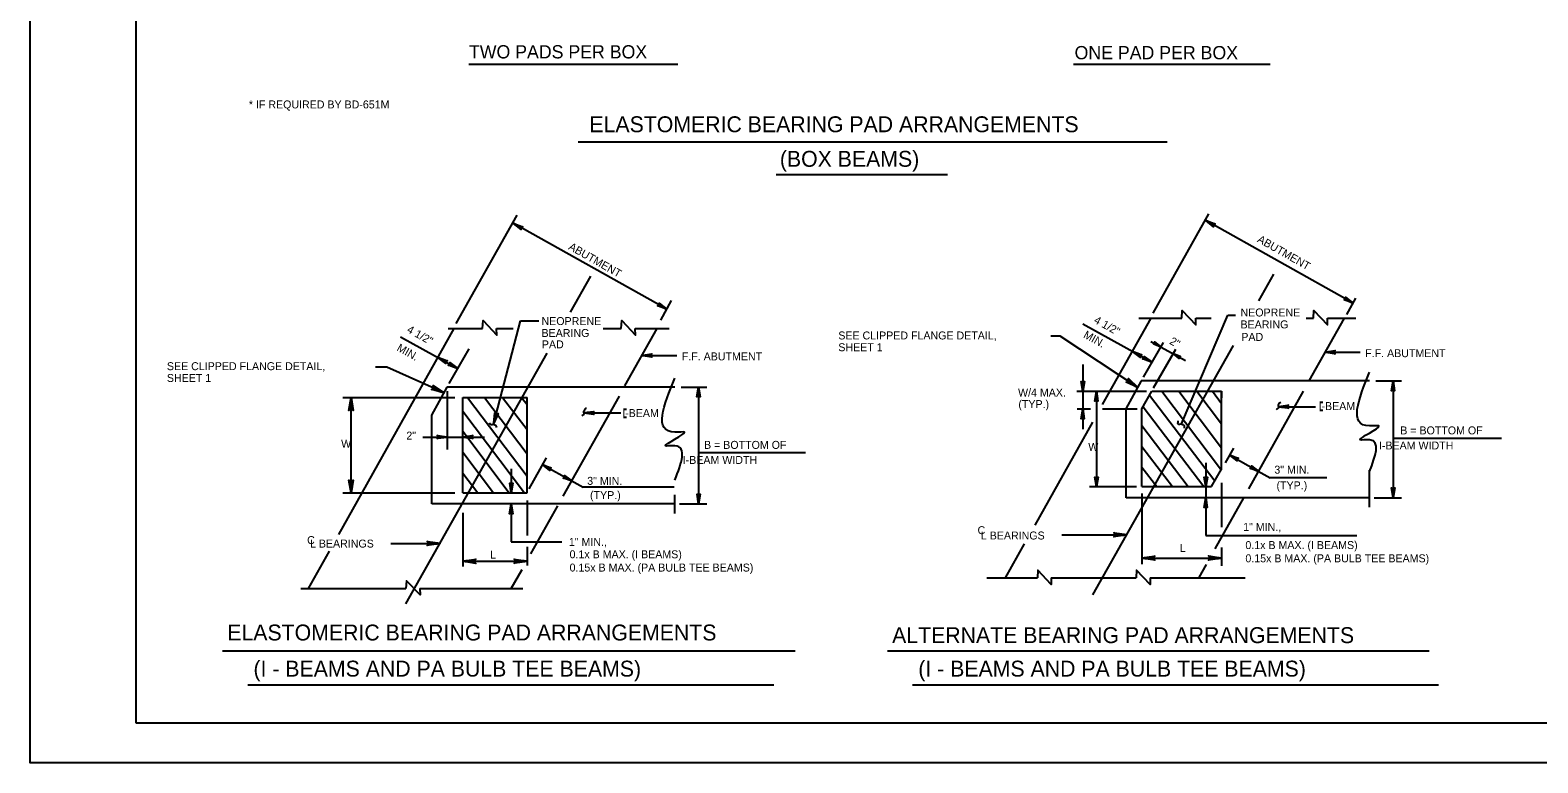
# Model space of a CAD drawing. Extents: x 639028 to 640031, y 298558 to 299746.
# Drawn here: x 639028 to 639597, y 298558 to 298835 of the extents above; entities that cross this region are included whole.
import ezdxf

# ---------------------------------------------------------------- set-up
doc = ezdxf.new("R2010")
doc.units = 0
doc.layers.add('1', color=7, linetype='Continuous')
doc.layers.add('PLT-BNDY', color=7, linetype='Continuous')

msp = doc.modelspace()

# ---------------------------------------------------------------- linework, layer by layer
at = {"layer": '1'}
for p, q in [((639067.87, 298573.33), (639067.87, 299137.33)), ((639193.44, 298821.9), (639272.25, 298821.9)), ((639421.49, 298821.9), (639495.7, 298821.9)), ((639234.68, 298792.59), (639456.81, 298792.59)), ((639309.33, 298780.24), (639373.96, 298780.24)), ((639188.59, 298724.09), (639211.59, 298764.96)), ((639268.09, 298729.46), (639210.09, 298761.96)), ((639451.57, 298727.98), (639472.58, 298765.41)), ((639527.1, 298731.76), (639471.48, 298762.89)), ((639231.73, 298728.37), (639239.39, 298741.96)), ((639491.42, 298732.69), (639497.05, 298742.67)), ((639265.84, 298725.34), (639269.84, 298732.71)), ((639524.7, 298727.48), (639528.09, 298733.6)), ((639432.5, 298693.5), (639450.79, 298726.1)), ((639446.2, 298726.1), (639462.39, 298726.1)), ((639462.23, 298686.17), (639479.73, 298727.17)), ((639467.64, 298726.1), (639473.52, 298726.1)), ((639479.73, 298727.17), (639482.6, 298727.17)), ((639509.37, 298726.1), (639512.05, 298726.1)), ((639510.48, 298702.42), (639523.83, 298726.1)), ((639517.3, 298726.1), (639528.07, 298726.1)), ((639144.34, 298644.49), (639187.86, 298722.21)), ((639185.59, 298722.21), (639198.58, 298722.21)), ((639202.88, 298686.52), (639212.85, 298725.11)), ((639203.83, 298722.21), (639210.14, 298722.21)), ((639212.85, 298725.11), (639219.81, 298725.11)), ((639244.1, 298722.21), (639250.88, 298722.21)), ((639252.25, 298700.54), (639264.47, 298722.21)), ((639256.13, 298722.21), (639268.97, 298722.21)), ((639425.01, 298723.98), (639451.19, 298709.44)), ((639167.55, 298719.1), (639189.21, 298707.06)), ((639186, 298701.42), (639193.48, 298714.57)), ((639416.55, 298719.31), (639413.02, 298719.31)), ((639445.86, 298699.97), (639416.55, 298719.31)), ((639428.86, 298621.71), (639481.87, 298715.73)), ((639447.98, 298703.79), (639455.45, 298716.94)), ((639450.69, 298717.35), (639463.78, 298710.08)), ((639451.73, 298699.79), (639460.17, 298714.43)), ((639169.67, 298618.29), (639222.97, 298712.83)), ((639258.74, 298712.05), (639271.87, 298712.05)), ((639425.1, 298708.64), (639425.1, 298684.21)), ((639516.59, 298713.26), (639529.72, 298713.26)), ((639162.47, 298707.6), (639158.21, 298707.6)), ((639184.08, 298697.95), (639162.47, 298707.6)), ((639179.38, 298689.54), (639185.25, 298700.04)), ((639271.13, 298700.04), (639185.13, 298700.04)), ((639185.38, 298676.54), (639185.38, 298698.54)), ((639273.5, 298700.04), (639283.13, 298700.04)), ((639280, 298700.04), (639280, 298656.04)), ((639422.73, 298698.54), (639449.1, 298698.54)), ((639430.23, 298698.54), (639430.23, 298662.54)), ((639441.35, 298691.92), (639447.23, 298702.42)), ((639533.23, 298702.42), (639447.1, 298702.42)), ((639447.35, 298691.92), (639451.1, 298698.54)), ((639451.1, 298698.54), (639477.35, 298698.54)), ((639454.85, 298698.54), (639477.35, 298668.79)), ((639461.23, 298698.54), (639477.35, 298677.17)), ((639468.1, 298698.54), (639477.35, 298686.29)), ((639473.98, 298698.54), (639477.35, 298693.92)), ((639477.35, 298669.17), (639477.35, 298698.54)), ((639477.35, 298698.54), (639477.36, 298696.06)), ((639487.67, 298661.72), (639508.29, 298698.51)), ((639535.6, 298702.42), (639545.23, 298702.42)), ((639542.1, 298702.42), (639542.1, 298658.29)), ((639145.83, 298696.17), (639188.14, 298696.17)), ((639148.94, 298660.17), (639148.94, 298696.17)), ((639191.13, 298696.17), (639215.38, 298696.17)), ((639191.13, 298660.17), (639191.13, 298696.17)), ((639192.88, 298696.17), (639215.38, 298666.54)), ((639199.25, 298696.17), (639215.38, 298674.92)), ((639206.13, 298696.17), (639215.38, 298684.04)), ((639213.25, 298696.17), (639215.38, 298693.54)), ((639215.38, 298660.17), (639215.38, 298696.17)), ((639229.04, 298658.92), (639250.19, 298696.72)), ((639251.75, 298691.79), (639252.88, 298691.79)), ((639422.85, 298691.92), (639427.99, 298691.92)), ((639432.52, 298691.92), (639445.6, 298691.92)), ((639441.35, 298658.29), (639441.35, 298691.92)), ((639447.35, 298662.54), (639447.35, 298691.92)), ((639447.85, 298692.67), (639470.73, 298662.54)), ((639450.23, 298697.04), (639474.85, 298664.67)), ((639498.85, 298692.67), (639512.85, 298692.67)), ((639514.48, 298694.42), (639515.6, 298694.42)), ((639179.38, 298656.04), (639179.38, 298689.54)), ((639191.13, 298691.04), (639214.38, 298660.17)), ((639236.88, 298690.42), (639250.75, 298690.42)), ((639251.75, 298688.79), (639252.88, 298688.79)), ((639407.01, 298648.06), (639428.76, 298686.83)), ((639514.48, 298691.42), (639515.6, 298691.42)), ((639176.04, 298681.17), (639185.13, 298681.17)), ((639185.13, 298681.17), (639191.13, 298681.17)), ((639191.13, 298683.42), (639208.63, 298660.17)), ((639191.13, 298681.17), (639199.25, 298681.17)), ((639447.35, 298685.54), (639464.85, 298662.54)), ((639542.1, 298680.82), (639583.07, 298680.82)), ((639191.13, 298675.54), (639202.75, 298660.17)), ((639280.14, 298675.36), (639320.38, 298675.36)), ((639447.35, 298677.67), (639458.85, 298662.54)), ((639478.85, 298671.54), (639481.98, 298677.04)), ((639209.38, 298669.29), (639209.38, 298660.17)), ((639216.13, 298661.67), (639222.75, 298673.42)), ((639221.25, 298670.79), (639232.25, 298664.67)), ((639447.35, 298669.92), (639452.98, 298662.54)), ((639471.48, 298671.54), (639471.48, 298662.54)), ((639473.6, 298662.54), (639477.35, 298669.17)), ((639480.48, 298674.42), (639491.48, 298668.29)), ((639533.23, 298661.41), (639533.23, 298668.73)), ((639191.13, 298667.67), (639196.75, 298660.17)), ((639232, 298664.79), (639236.5, 298662.29)), ((639477.35, 298663.94), (639477.35, 298647.29)), ((639491.23, 298668.42), (639495.73, 298665.92)), ((639517.16, 298665.92), (639495.73, 298665.92)), ((639145.83, 298660.17), (639188.14, 298660.17)), ((639191.13, 298660.17), (639215.38, 298660.17)), ((639270.84, 298662.29), (639236.5, 298662.29)), ((639271.13, 298652.42), (639271.13, 298659.42)), ((639427.6, 298662.54), (639445.35, 298662.54)), ((639533.23, 298658.29), (639441.35, 298658.29)), ((639447.35, 298662.54), (639473.6, 298662.54)), ((639447.35, 298659.92), (639447.35, 298633.3)), ((639471.48, 298662.54), (639471.48, 298644.04)), ((639475.01, 298639.06), (639485.85, 298658.29)), ((639533.23, 298654.79), (639533.23, 298662.92)), ((639534.98, 298658.29), (639545.23, 298658.29)), ((639271.13, 298656.04), (639179.38, 298656.04)), ((639191.13, 298652.68), (639191.13, 298632.45)), ((639209.38, 298656.04), (639209.38, 298641.67)), ((639215.38, 298657.32), (639215.38, 298644.04)), ((639216.78, 298637.14), (639227, 298655.29)), ((639272.88, 298656.04), (639283.13, 298656.04)), ((639163.93, 298641.08), (639182.52, 298641.08)), ((639209.38, 298641.67), (639228.5, 298641.67)), ((639395.83, 298628.13), (639402.99, 298640.9)), ((639417.14, 298644.38), (639441.64, 298644.38)), ((639471.48, 298644.04), (639528.43, 298644.04)), ((639132.89, 298624.05), (639140.82, 298638.2)), ((639215.38, 298639.85), (639215.38, 298632.78)), ((639447.35, 298635.59), (639477.35, 298635.59)), ((639477.35, 298639.56), (639477.35, 298632.64)), ((639191.13, 298634.38), (639215.38, 298634.38)), ((639209.41, 298624.05), (639213.47, 298631.25)), ((639468.92, 298628.25), (639471.68, 298633.15)), ((639130.02, 298624.05), (639169.64, 298624.05)), ((639174.89, 298624.05), (639213.77, 298624.05)), ((639388.82, 298628.12), (639407.9, 298628.12)), ((639413.15, 298628.12), (639445.17, 298628.12)), ((639450.42, 298628.12), (639486.3, 298628.12)), ((639100.5, 298600.62), (639316.46, 298600.62)), ((639351.34, 298600.62), (639555.72, 298600.62)), ((639110, 298587.75), (639308.41, 298587.75)), ((639360.84, 298587.75), (639559.25, 298587.75)), ((639853.87, 298573.33), (639067.87, 298573.33))]:
    msp.add_line(p, q, dxfattribs=at)
for points in [[(639212.97, 298759.71), (639212.97, 298760.09), (639210.22, 298761.84), (639212.97, 298759.71), (639213.09, 298759.59), (639210.22, 298761.84), (639213.22, 298760.34), (639213.47, 298760.46), (639210.22, 298761.84), (639213.72, 298760.59), (639213.47, 298760.46)], [(639474.35, 298760.76), (639474.35, 298761.01), (639471.48, 298762.89), (639474.35, 298760.76), (639474.35, 298760.51), (639471.48, 298762.89), (639474.48, 298761.39), (639474.73, 298761.51), (639471.48, 298762.89), (639474.98, 298761.64), (639474.73, 298761.51)], [(639265.22, 298731.59), (639265.22, 298731.21), (639268.09, 298729.46), (639265.22, 298731.59), (639265.22, 298731.71), (639268.09, 298729.46), (639265.09, 298730.96), (639264.84, 298730.84), (639268.09, 298729.46), (639264.59, 298730.71), (639264.84, 298730.84)], [(639524.23, 298733.89), (639524.23, 298733.51), (639527.1, 298731.76), (639524.23, 298733.89), (639524.1, 298734.01), (639527.1, 298731.76), (639524.1, 298733.26), (639523.85, 298733.14), (639527.1, 298731.76), (639523.6, 298733.01), (639523.85, 298733.14)], [(639462.39, 298726.1), (639462.51, 298728.98), (639467.64, 298723.6), (639467.64, 298726.1)], [(639512.05, 298726.1), (639512.18, 298728.98), (639517.3, 298723.6), (639517.3, 298726.1)], [(639198.58, 298722.21), (639198.83, 298725.21), (639203.96, 298719.71), (639203.83, 298722.21)], [(639250.88, 298722.21), (639251.13, 298725.21), (639256.25, 298719.71), (639256.13, 298722.21)], [(639452.26, 298717.02), (639452.26, 298716.77), (639454.51, 298715.27), (639452.26, 298717.02), (639452.13, 298717.15), (639454.51, 298715.27), (639452.13, 298716.52), (639451.88, 298716.4), (639454.51, 298715.27), (639451.76, 298716.4), (639451.88, 298716.4)], [(639184.59, 298709.2), (639184.6, 298709.48), (639181.71, 298711.23), (639184.59, 298709.2), (639184.75, 298708.97), (639181.71, 298711.23), (639184.78, 298709.81), (639185.01, 298709.97), (639181.71, 298711.23), (639185.29, 298709.95), (639185.01, 298709.97)], [(639186.34, 298709.09), (639186.32, 298708.81), (639189.21, 298707.06), (639186.34, 298709.09), (639186.18, 298709.32), (639189.21, 298707.06), (639186.14, 298708.48), (639185.91, 298708.32), (639189.21, 298707.06), (639185.63, 298708.34), (639185.91, 298708.32)], [(639262.12, 298711.67), (639261.99, 298711.8), (639258.74, 298712.05), (639262.12, 298711.67), (639262.37, 298711.42), (639258.74, 298712.05), (639261.99, 298712.17), (639262.12, 298712.42), (639258.74, 298712.05), (639262.37, 298712.67), (639262.12, 298712.42)], [(639446.63, 298711.54), (639446.64, 298711.82), (639443.75, 298713.57), (639446.63, 298711.54), (639446.79, 298711.31), (639443.75, 298713.57), (639446.82, 298712.15), (639447.06, 298712.3), (639443.75, 298713.57), (639447.33, 298712.29), (639447.06, 298712.3)], [(639448.31, 298711.46), (639448.3, 298711.18), (639451.19, 298709.44), (639448.31, 298711.46), (639448.15, 298711.69), (639451.19, 298709.44), (639448.11, 298710.86), (639447.88, 298710.7), (639451.19, 298709.44), (639447.6, 298710.71), (639447.88, 298710.7)], [(639461.45, 298710.98), (639461.45, 298711.23), (639459.2, 298712.6), (639461.45, 298710.98), (639461.45, 298710.85), (639459.2, 298712.6), (639461.58, 298711.48), (639461.83, 298711.6), (639459.2, 298712.6), (639461.95, 298711.6), (639461.83, 298711.6)], [(639519.97, 298712.76), (639519.84, 298713.01), (639516.59, 298713.26), (639519.97, 298712.76), (639520.22, 298712.64), (639516.59, 298713.26), (639519.84, 298713.39), (639519.97, 298713.64), (639516.59, 298713.26), (639520.22, 298713.89), (639519.97, 298713.64)], [(639442.33, 298702.99), (639442.29, 298702.62), (639445.86, 298699.97), (639442.33, 298702.99), (639442.24, 298703.29), (639445.86, 298699.97), (639442.03, 298702.23), (639441.72, 298702.04), (639445.86, 298699.97), (639441.39, 298701.99), (639441.72, 298702.04)], [(639180.11, 298700.37), (639180.13, 298699.99), (639184.08, 298697.95), (639180.11, 298700.37), (639179.98, 298700.65), (639184.08, 298697.95), (639179.95, 298699.57), (639179.66, 298699.33), (639184.08, 298697.95), (639179.34, 298699.23), (639179.66, 298699.33)], [(639279.63, 298696.54), (639279.88, 298696.67), (639280, 298700.04), (639279.63, 298696.54), (639279.38, 298696.42), (639280, 298700.04), (639280.25, 298696.67), (639280.5, 298696.54), (639280, 298700.04), (639280.63, 298696.42), (639280.5, 298696.54)], [(639425.48, 298701.92), (639425.23, 298701.92), (639425.1, 298698.54), (639425.48, 298701.92), (639425.73, 298702.17), (639425.1, 298698.54), (639424.98, 298701.92), (639424.73, 298701.92), (639425.1, 298698.54), (639424.48, 298702.17), (639424.73, 298701.92)], [(639429.73, 298695.04), (639429.98, 298695.17), (639430.23, 298698.54), (639429.73, 298695.04), (639429.6, 298694.79), (639430.23, 298698.54), (639430.35, 298695.17), (639430.6, 298695.04), (639430.23, 298698.54), (639430.73, 298694.79), (639430.6, 298695.04)], [(639541.6, 298698.92), (639541.85, 298699.04), (639542.1, 298702.42), (639541.6, 298698.92), (639541.48, 298698.67), (639542.1, 298702.42), (639542.23, 298699.04), (639542.48, 298698.92), (639542.1, 298702.42), (639542.6, 298698.67), (639542.48, 298698.92)], [(639148.36, 298691.55), (639148.69, 298691.72), (639148.94, 298696.17), (639148.36, 298691.55), (639148.16, 298691.32), (639148.94, 298696.17), (639149.16, 298691.73), (639149.49, 298691.57), (639148.94, 298696.17), (639149.71, 298691.32), (639149.49, 298691.57)], [(639424.6, 298688.42), (639424.85, 298688.54), (639425.1, 298691.92), (639424.6, 298688.42), (639424.48, 298688.17), (639425.1, 298691.92), (639425.23, 298688.54), (639425.48, 298688.42), (639425.1, 298691.92), (639425.6, 298688.17), (639425.48, 298688.42)], [(639502.35, 298692.29), (639502.23, 298692.54), (639498.85, 298692.67), (639502.35, 298692.29), (639502.6, 298692.17), (639498.85, 298692.67), (639502.23, 298692.92), (639502.35, 298693.17), (639498.85, 298692.67), (639502.6, 298693.29), (639502.35, 298693.17)], [(639204.25, 298689.97), (639203.96, 298689.91), (639202.88, 298686.52), (639204.25, 298689.97), (639204.46, 298690.12), (639202.88, 298686.52), (639203.6, 298690), (639203.37, 298690.19), (639202.88, 298686.52), (639203.25, 298690.43), (639203.37, 298690.19)], [(639240.38, 298689.92), (639240.25, 298690.17), (639236.88, 298690.42), (639240.38, 298689.92), (639240.5, 298689.79), (639236.88, 298690.42), (639240.25, 298690.54), (639240.38, 298690.79), (639236.88, 298690.42), (639240.5, 298690.92), (639240.38, 298690.79)], [(639181.63, 298681.67), (639181.75, 298681.42), (639185.13, 298681.17), (639181.63, 298681.67), (639181.5, 298681.79), (639185.13, 298681.17), (639181.75, 298681.04), (639181.63, 298680.79), (639185.13, 298681.17), (639181.5, 298680.67), (639181.63, 298680.79)], [(639194.63, 298680.79), (639194.5, 298681.04), (639191.13, 298681.17), (639194.63, 298680.79), (639194.88, 298680.67), (639191.13, 298681.17), (639194.5, 298681.42), (639194.63, 298681.67), (639191.13, 298681.17), (639194.88, 298681.79), (639194.63, 298681.67)], [(639223.88, 298668.92), (639223.88, 298669.17), (639221.25, 298670.79), (639223.88, 298668.92), (639224, 298668.67), (639221.25, 298670.79), (639224, 298669.42), (639224.25, 298669.54), (639221.25, 298670.79), (639224.5, 298669.67), (639224.25, 298669.54)], [(639223.88, 298668.92), (639223.88, 298669.17), (639221.25, 298670.79), (639223.88, 298668.92), (639224, 298668.67), (639221.25, 298670.79), (639224, 298669.42), (639224.25, 298669.54), (639221.25, 298670.79), (639224.5, 298669.67), (639224.25, 298669.54)], [(639483.1, 298672.54), (639483.1, 298672.79), (639480.48, 298674.42), (639483.1, 298672.54), (639483.23, 298672.29), (639480.48, 298674.42), (639483.23, 298673.04), (639483.48, 298673.17), (639480.48, 298674.42), (639483.73, 298673.29), (639483.48, 298673.17)], [(639483.1, 298672.54), (639483.1, 298672.79), (639480.48, 298674.42), (639483.1, 298672.54), (639483.23, 298672.29), (639480.48, 298674.42), (639483.23, 298673.04), (639483.48, 298673.17), (639480.48, 298674.42), (639483.73, 298673.29), (639483.48, 298673.17)], [(639488.85, 298670.17), (639488.85, 298669.92), (639491.48, 298668.29), (639488.85, 298670.17), (639488.73, 298670.42), (639491.48, 298668.29), (639488.73, 298669.67), (639488.48, 298669.54), (639491.48, 298668.29), (639488.23, 298669.42), (639488.48, 298669.54)], [(639149.52, 298664.78), (639149.18, 298664.61), (639148.94, 298660.17), (639149.52, 298664.78), (639149.72, 298665.01), (639148.94, 298660.17), (639148.72, 298664.6), (639148.39, 298664.77), (639148.94, 298660.17), (639148.17, 298665.01), (639148.39, 298664.77)], [(639209.88, 298663.67), (639209.63, 298663.54), (639209.38, 298660.17), (639209.88, 298663.67), (639210, 298663.79), (639209.38, 298660.17), (639209.25, 298663.54), (639209, 298663.67), (639209.38, 298660.17), (639208.88, 298663.79), (639209, 298663.67)], [(639229.63, 298666.54), (639229.63, 298666.29), (639232.25, 298664.67), (639229.63, 298666.54), (639229.5, 298666.79), (639232.25, 298664.67), (639229.5, 298666.04), (639229.25, 298665.92), (639232.25, 298664.67), (639229, 298665.79), (639229.25, 298665.92)], [(639430.6, 298665.92), (639430.35, 298665.92), (639430.23, 298662.54), (639430.6, 298665.92), (639430.85, 298666.17), (639430.23, 298662.54), (639430.1, 298665.92), (639429.85, 298665.92), (639430.23, 298662.54), (639429.6, 298666.17), (639429.85, 298665.92)], [(639471.85, 298665.92), (639471.6, 298665.92), (639471.48, 298662.54), (639471.85, 298665.92), (639472.1, 298666.17), (639471.48, 298662.54), (639471.23, 298665.92), (639470.98, 298665.92), (639471.48, 298662.54), (639470.85, 298666.17), (639470.98, 298665.92)], [(639280.5, 298659.54), (639280.25, 298659.42), (639280, 298656.04), (639280.5, 298659.54), (639280.63, 298659.67), (639280, 298656.04), (639279.88, 298659.42), (639279.63, 298659.54), (639280, 298656.04), (639279.5, 298659.67), (639279.63, 298659.54)], [(639470.98, 298654.79), (639471.23, 298654.92), (639471.48, 298658.29), (639470.98, 298654.79), (639470.85, 298654.67), (639471.48, 298658.29), (639471.6, 298654.92), (639471.85, 298654.79), (639471.48, 298658.29), (639471.98, 298654.67), (639471.85, 298654.79)], [(639542.48, 298661.79), (639542.23, 298661.67), (639542.1, 298658.29), (639542.48, 298661.79), (639542.73, 298662.04), (639542.1, 298658.29), (639541.85, 298661.67), (639541.73, 298661.79), (639542.1, 298658.29), (639541.48, 298662.04), (639541.73, 298661.79)], [(639209, 298652.54), (639209.25, 298652.67), (639209.38, 298656.04), (639209, 298652.54), (639208.75, 298652.29), (639209.38, 298656.04), (639209.63, 298652.67), (639209.75, 298652.54), (639209.38, 298656.04), (639210, 298652.29), (639209.75, 298652.54)], [(639177.91, 298641.66), (639178.08, 298641.32), (639182.52, 298641.08), (639177.91, 298641.66), (639177.67, 298641.86), (639182.52, 298641.08), (639178.08, 298640.86), (639177.92, 298640.53), (639182.52, 298641.08), (639177.67, 298640.31), (639177.92, 298640.53)], [(639437.03, 298644.96), (639437.2, 298644.63), (639441.64, 298644.38), (639437.03, 298644.96), (639436.79, 298645.17), (639441.64, 298644.38), (639437.21, 298644.16), (639437.04, 298643.83), (639441.64, 298644.38), (639436.79, 298643.61), (639437.04, 298643.83)], [(639195.74, 298633.8), (639195.57, 298634.14), (639191.13, 298634.38), (639195.74, 298633.8), (639195.98, 298633.6), (639191.13, 298634.38), (639195.57, 298634.6), (639195.73, 298634.93), (639191.13, 298634.38), (639195.98, 298635.15), (639195.73, 298634.93)], [(639210.77, 298634.96), (639210.94, 298634.63), (639215.38, 298634.38), (639210.77, 298634.96), (639210.53, 298635.17), (639215.38, 298634.38), (639210.94, 298634.16), (639210.78, 298633.83), (639215.38, 298634.38), (639210.53, 298633.61), (639210.78, 298633.83)], [(639451.97, 298635.01), (639451.79, 298635.35), (639447.35, 298635.59), (639451.97, 298635.01), (639452.2, 298634.81), (639447.35, 298635.59), (639451.79, 298635.81), (639451.95, 298636.14), (639447.35, 298635.59), (639452.2, 298636.36), (639451.95, 298636.14)], [(639472.74, 298636.17), (639472.91, 298635.84), (639477.35, 298635.59), (639472.74, 298636.17), (639472.5, 298636.38), (639477.35, 298635.59), (639472.92, 298635.37), (639472.75, 298635.04), (639477.35, 298635.59), (639472.5, 298634.82), (639472.75, 298635.04)], [(639413.15, 298628.12), (639413.15, 298625.62), (639408.02, 298630.99), (639407.9, 298628.12)], [(639450.42, 298628.12), (639450.42, 298625.62), (639445.3, 298630.99), (639445.17, 298628.12)], [(639174.89, 298624.05), (639175.02, 298621.67), (639169.89, 298627.05), (639169.64, 298624.05)]]:
    msp.add_lwpolyline(points, dxfattribs=at)
for points in [[(639271.13, 298665.04), (639271.13, 298677.92), (639267.63, 298677.92), (639274.75, 298683.04), (639271.13, 298683.04), (639271.13, 298703.42)], [(639533.23, 298668.29), (639533.23, 298680.17), (639529.73, 298680.17), (639536.73, 298685.42), (639533.23, 298685.42), (639533.23, 298705.67)], [(639237.75, 298692.04), (639237.13, 298691.79), (639236.88, 298691.29), (639236.63, 298690.92), (639236.75, 298690.29), (639236.75, 298689.92), (639236.5, 298689.54), (639236, 298689.29)], [(639499.73, 298694.29), (639499.23, 298694.04), (639498.85, 298693.67), (639498.73, 298693.29), (639498.85, 298692.67), (639498.73, 298692.17), (639498.48, 298691.92), (639497.98, 298691.54)], [(639203.92, 298684.85), (639203.67, 298685.47), (639203.17, 298685.72), (639202.8, 298685.97), (639202.17, 298685.85), (639201.8, 298685.85), (639201.42, 298686.1), (639201.17, 298686.6)], [(639460.85, 298687.42), (639460.85, 298686.79), (639460.85, 298686.29), (639461.27, 298686.13), (639462.1, 298686.17), (639462.6, 298686.04), (639463.08, 298685.8), (639463.32, 298684.64)]]:
    msp.add_spline(points, degree=3, dxfattribs=at)
at = {"layer": 'PLT-BNDY'}
msp.add_lwpolyline([(639027.87, 299152.33), (639868.87, 299152.33), (639868.87, 298558.33), (639027.87, 298558.33)], close=True, dxfattribs=at)

# ---------------------------------------------------------------- texts
at = {"layer": '1'}
for s, height, p in [('TWO PADS PER BOX', 4.9999, (639193.43, 298824.09)), ('ONE PAD PER BOX', 4.9999, (639421.93, 298823.77)), ('* IF REQUIRED BY BD-651M', 3, (639110.39, 298805.23)), ('ELASTOMERIC BEARING PAD ARRANGEMENTS', 6, (639238.88, 298796.25)), ('(BOX BEAMS)', 6, (639310.73, 298783.21)), ('NEOPRENE', 3, (639220.81, 298723.5)), ('NEOPRENE', 3, (639484.54, 298726.74)), ('BEARING', 3, (639220.81, 298719)), ('SEE CLIPPED FLANGE DETAIL,', 3, (639332.79, 298718.07)), ('BEARING', 3, (639484.54, 298722.24)), ('PAD', 3, (639484.85, 298717.52)), ('PAD', 3, (639220.94, 298714.71)), ('SHEET 1', 3, (639332.79, 298713.63)), ('F.F. ABUTMENT', 3, (639531.59, 298711.39)), ('SEE CLIPPED FLANGE DETAIL,', 3, (639079.47, 298706.48)), ('F.F. ABUTMENT', 3, (639273.74, 298710.17)), ('SHEET 1', 3, (639079.47, 298702.04)), ('W/4 MAX.', 3, (639400.6, 298696.54)), ('I-BEAM', 3, (639251.25, 298688.79)), ('(TYP.)', 3, (639400.73, 298692.17)), ('I-BEAM', 3, (639513.98, 298691.42)), ('W', 3, (639145.21, 298677.21)), ('2"', 3, (639169.81, 298680.28)), ('B = BOTTOM OF', 3, (639544.81, 298682.25)), ('B = BOTTOM OF', 3, (639282.13, 298676.79)), ('W', 3, (639427.1, 298676.04)), ('    I-BEAM WIDTH', 3, (639532.31, 298676.56)), ('    I-BEAM WIDTH', 3, (639269.63, 298671.1)), ('3" MIN.', 3, (639497.31, 298667.44)), ('3" MIN.', 3, (639238.05, 298663.21)), ('(TYP.)', 3, (639498.12, 298661.52)), ('(TYP.)', 3, (639239.11, 298657.84)), ('C', 3, (639385.33, 298644.61)), ('1" MIN.,', 3, (639485.54, 298645.82)), ('C', 3, (639132.37, 298640.87)), ('L BEARINGS', 3, (639133.45, 298639.55)), ('1" MIN.,', 3, (639231.13, 298640.17)), ('L BEARINGS', 3, (639386.57, 298642.6)), ('L', 3, (639461.65, 298637.9)), ('0.1x B MAX. (I BEAMS)', 3, (639486.38, 298638.99)), ('L', 3, (639201.41, 298635.37)), ('0.1x B MAX. (I BEAMS)', 3, (639231.4, 298635.51)), ('0.15x B MAX. (PA BULB TEE BEAMS)', 3, (639486.38, 298633.99)), ('0.15x B MAX. (PA BULB TEE BEAMS)', 3, (639231.4, 298630.51)), ('ELASTOMERIC BEARING PAD ARRANGEMENTS', 6, (639102.25, 298604.5)), ('ALTERNATE BEARING PAD ARRANGEMENTS', 6, (639353.09, 298603.5)), ('(I - BEAMS AND PA BULB TEE BEAMS)', 6, (639112.13, 298590.87)), ('(I - BEAMS AND PA BULB TEE BEAMS)', 6, (639362.97, 298590.87))]:
    msp.add_text(s, height=height, dxfattribs=at).set_placement(p)
for s, rotation, p in [('ABUTMENT', 330.3486, (639230.72, 298752.21)), ('ABUTMENT', 330.3486, (639490.6, 298755.01)), ('4 1/2"', 330.7223, (639428.96, 298724.51)), ('4 1/2"', 330.7223, (639169.74, 298720.97)), ('MIN.', 330.7223, (639425.01, 298718.96)), ('MIN.', 330.7223, (639165.95, 298714.04)), ('2"', 330.9454, (639457.49, 298716.55))]:
    msp.add_text(s, height=3, rotation=rotation, dxfattribs=at).set_placement(p)

doc.saveas('drawing.dxf')
